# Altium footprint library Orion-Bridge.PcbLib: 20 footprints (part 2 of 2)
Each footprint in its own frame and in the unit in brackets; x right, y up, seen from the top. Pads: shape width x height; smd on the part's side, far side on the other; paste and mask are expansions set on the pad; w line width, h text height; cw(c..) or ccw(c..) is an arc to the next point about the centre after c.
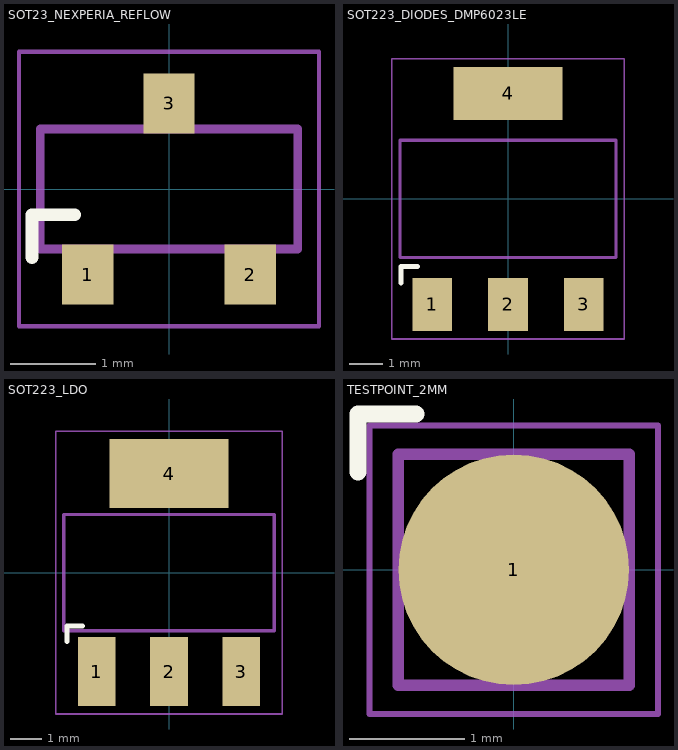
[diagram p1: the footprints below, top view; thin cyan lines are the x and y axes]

## SOT23_NEXPERIA_REFLOW [mm] "Nexperia SOT23 reflow footprint Fig10: 0.6 x 0.7 copper lands, 1.9 pin pitch and 2.0 row centres. Drawing is rotated 180 degrees to match existing top-view pin1 lower left, pin2 lower right, pin3 upper centre. Paste suggested0.5 x0.6, mask opening1.0 x1.0; set fabrication-specific expansions accordingly."
height 1.1
pads (3):
  rect 0.6x0.7 smd: 1(-0.95,-1) 2(0.95,-1) 3(0,1)
Top Overlay:
  lines w0.15: -1.6,-0.8 -1.6,-0.3 -1.1,-0.3
Component bodies:
  lines w0.1: -1.5,-0.7 1.5,-0.7 1.5,0.7 -1.5,0.7 -1.5,-0.7
Courtyards:
  lines w0.05: -1.75,-1.6 1.75,-1.6 1.75,1.6 -1.75,1.6 -1.75,-1.6
3D body: height 1.1, standoff 0.12, extent -1.5,-0.7 1.5,0.7
3D body: height 0.28, standoff 0.02, extent -1.19,-1.3 -0.71,-0.35
3D body: height 0.28, standoff 0.02, extent 0.71,-1.3 1.19,-0.35
3D body: height 0.28, standoff 0.02, extent -0.24,0.35 0.24,1.3
3D body: height 1.11, standoff 1.1, extent -1.12,0.232 -0.8,0.552

## SOT223_DIODES_DMP6023LE [mm] "Diodes DMP6023LE datasheet suggested SOT223 pad layout: C=2.30, C1=6.40, X=1.20, X1=3.30, Y=Y1=1.60. Pin 1 gate, 2 drain, 3 source, 4 drain tab."
height 1.65
pads (4):
  rect 1.2x1.6 smd: 1(-2.3,-3.2) 2(0,-3.2) 3(2.3,-3.2)
  rect 3.3x1.6 smd: 4(0,3.2)
Top Overlay:
  lines w0.15: -3.25,-2.55 -3.25,-2.05 -2.75,-2.05
Component bodies:
  lines w0.1: -3.275,-1.775 3.275,-1.775 3.275,1.775 -3.275,1.775 -3.275,-1.775
Courtyards:
  lines w0.05: -3.525,-4.25 3.525,-4.25 3.525,4.25 -3.525,4.25 -3.525,-4.25
3D body: height 1.65, standoff 0.12, extent -3.275,-1.775 3.275,1.775
3D body: height 0.28, standoff 0.02, extent -2.725,-3.525 -1.875,-1.45
3D body: height 0.28, standoff 0.02, extent -0.425,-3.525 0.425,-1.45
3D body: height 0.28, standoff 0.02, extent 1.875,-3.525 2.725,-1.45
3D body: height 0.28, standoff 0.02, extent -1.402,1.45 1.402,3.525
3D body: height 1.67, standoff 1.65, extent -2.256,0.834 -1.936,1.154

## SOT223_LDO [mm] "TI TPS7B69-Q1 DCY package drawing4202506/B p20: maximum body6.7x3.7, maximum height1.8, lead pitch2.3. Existing R2 engineering lands retained: 1.2x2.2 signal pads,3.8x2.2 tab,6.3 row centres. TI datasheet provides no DCY recommended land pattern; qualify solder process. Pin4 is GND_BUS tab."
height 1.8
pads (4):
  rect 1.2x2.2 smd: 1(-2.3,-3.15) 2(0,-3.15) 3(2.3,-3.15)
  rect 3.8x2.2 smd: 4(0,3.15)
Top Overlay:
  lines w0.15: -3.25,-2.2 -3.25,-1.7 -2.75,-1.7
Component bodies:
  lines w0.1: -3.35,-1.85 3.35,-1.85 3.35,1.85 -3.35,1.85 -3.35,-1.85
Courtyards:
  lines w0.05: -3.6,-4.5 3.6,-4.5 3.6,4.5 -3.6,4.5 -3.6,-4.5
3D body: height 1.8, standoff 0.12, extent -3.35,-1.85 3.35,1.85
3D body: height 0.28, standoff 0.02, extent -2.725,-3.475 -1.875,-1.525
3D body: height 0.28, standoff 0.02, extent -0.425,-3.475 0.425,-1.525
3D body: height 0.28, standoff 0.02, extent 1.875,-3.475 2.725,-1.525
3D body: height 0.28, standoff 0.02, extent -1.6,1.525 1.6,3.475
3D body: height 1.82, standoff 1.8, extent -2.304,0.876 -1.984,1.196

## TESTPOINT_2MM [mm] "2 mm exposed top-copper test pad; no paste"
pads (1):
  round 2 smd: 1(0,0)
Top Overlay:
  lines w0.15: -1.35,0.85 -1.35,1.35 -0.85,1.35
Component bodies:
  lines w0.1: -1,-1 1,-1 1,1 -1,1 -1,-1
Courtyards:
  lines w0.05: -1.25,-1.25 1.25,-1.25 1.25,1.25 -1.25,1.25 -1.25,-1.25
3D body: height 0.04, standoff 0, extent -1,-1 1,1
